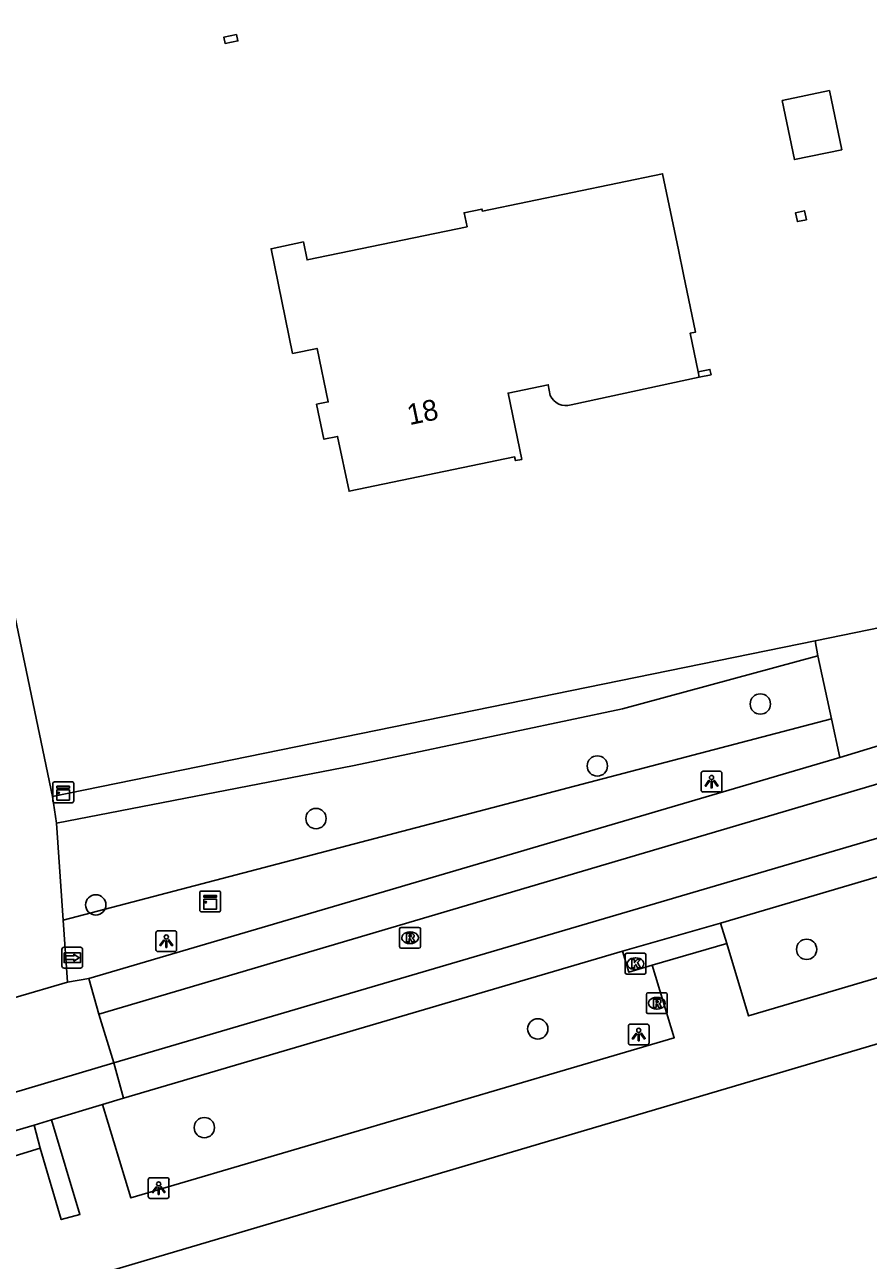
# Model space of a CAD drawing. Extents: x 162417 to 163721, y 384268 to 385416.
# Drawn here: x 163214.3 to 163254.9, y 384656 to 384715.4 of the extents above; entities that cross this region are included whole.
import ezdxf

# ---------------------------------------------------------------- set-up
doc = ezdxf.new("R2010")
doc.units = 0
for name, color, linetype in [('IMGEO_Boom', 7, 'Continuous'), ('IMGEO_Groenvoorziening', 7, 'Continuous'), ('IMGEO_Haag', 7, 'Continuous'), ('IMGEO_Kast', 7, 'Continuous'), ('IMGEO_Kolk', 7, 'Continuous'), ('IMGEO_Lichtpunt', 7, 'Continuous'), ('IMGEO_Muur', 7, 'Continuous'), ('IMGEO_Pand', 7, 'Continuous'), ('IMGEO_Pand_nummerreeks', 7, 'Continuous'), ('IMGEO_Rijbaan_lokaal_gesloten', 7, 'Continuous'), ('IMGEO_Rijbaan_lokaal_open', 7, 'Continuous'), ('IMGEO_Rioolput', 7, 'Continuous'), ('IMGEO_Voetpad_open', 7, 'Continuous'), ('IMGEO_Wegwijzer', 7, 'Continuous')]:
    doc.layers.add(name, color=color, linetype=linetype)

msp = doc.modelspace()

# ---------------------------------------------------------------- linework, layer by layer
at = {"layer": 'IMGEO_Boom'}
for centre in [(163249.675, 384682.735), (163241.835, 384679.753), (163228.302, 384677.22), (163217.707, 384673.066), (163251.902, 384670.927), (163238.971, 384667.097), (163222.929, 384662.346)]:
    msp.add_circle(centre, 0.489, dxfattribs=at)
at = {"layer": 'IMGEO_Groenvoorziening'}
msp.add_lwpolyline([(163253.099, 384682.014), (163216.145, 384672.327)], dxfattribs=at)
at = {"layer": 'IMGEO_Haag'}
for points in [[(163215.633, 384678.291), (163252.312, 384685.775)], [(163252.434, 384685.061), (163243.043, 384682.506), (163230.136, 384679.777), (163215.822, 384677.004)]]:
    msp.add_lwpolyline(points, dxfattribs=at)
at = {"layer": 'IMGEO_Kast'}
for p, q in [((163215.645, 384678.061), (163215.645, 384678.902)), ((163215.645, 384678.902), (163215.645, 384678.061)), ((163215.72, 384678.986), (163216.561, 384678.986)), ((163216.561, 384678.986), (163215.72, 384678.986)), ((163216.645, 384678.911), (163216.645, 384678.07)), ((163216.645, 384678.07), (163216.645, 384678.911)), ((163216.57, 384677.986), (163215.729, 384677.986)), ((163215.729, 384677.986), (163216.57, 384677.986)), ((163222.713, 384672.807), (163222.713, 384673.648)), ((163222.713, 384673.648), (163222.713, 384672.807)), ((163222.788, 384673.732), (163223.629, 384673.732)), ((163223.629, 384673.732), (163222.788, 384673.732)), ((163223.713, 384673.657), (163223.713, 384672.816)), ((163223.713, 384672.816), (163223.713, 384673.657)), ((163223.638, 384672.732), (163222.797, 384672.732)), ((163222.797, 384672.732), (163223.638, 384672.732))]:
    msp.add_line(p, q, dxfattribs=at)
for points in [[(163215.84, 384678.776), (163216.44, 384678.776), (163216.44, 384678.691), (163215.84, 384678.691), (163215.84, 384678.776)], [(163215.84, 384678.601), (163216.44, 384678.601), (163216.44, 384678.112), (163215.84, 384678.112), (163215.84, 384678.601)], [(163222.908, 384673.522), (163223.508, 384673.522), (163223.508, 384673.437), (163222.908, 384673.437), (163222.908, 384673.522)], [(163222.908, 384673.347), (163223.508, 384673.347), (163223.508, 384672.858), (163222.908, 384672.858), (163222.908, 384673.347)]]:
    msp.add_lwpolyline(points, dxfattribs=at)
for centre in [(163215.924, 384678.45), (163222.992, 384673.196)]:
    msp.add_circle(centre, 0.0377, dxfattribs=at)
for centre, start, end in [((163215.723, 384678.908), 92.4484, 184.28452), ((163215.723, 384678.908), 92.4484, 184.28452), ((163216.567, 384678.908), 2.4484, 94.28452), ((163216.567, 384678.908), 2.4484, 94.28452), ((163215.723, 384678.064), 182.4484, 274.28452), ((163215.723, 384678.064), 182.4484, 274.28452), ((163216.567, 384678.064), 272.4484, 4.28452), ((163216.567, 384678.064), 272.4484, 4.28452), ((163222.791, 384673.654), 92.4484, 184.28452), ((163222.791, 384673.654), 92.4484, 184.28452), ((163223.635, 384673.654), 2.4484, 94.28452), ((163223.635, 384673.654), 2.4484, 94.28452), ((163222.791, 384672.81), 182.4484, 274.28452), ((163222.791, 384672.81), 182.4484, 274.28452), ((163223.635, 384672.81), 272.4484, 4.28452), ((163223.635, 384672.81), 272.4484, 4.28452)]:
    msp.add_arc(centre, 0.0779, start, end, dxfattribs=at)
at = {"layer": 'IMGEO_Kolk'}
for p, q in [((163243.173, 384669.811), (163243.173, 384670.663)), ((163243.248, 384670.737), (163244.1, 384670.737)), ((163244.174, 384670.663), (163244.174, 384669.811)), ((163243.684, 384669.957), (163243.659, 384669.957)), ((163243.661, 384670.517), (163243.686, 384670.517)), ((163244.1, 384669.737), (163243.248, 384669.737))]:
    msp.add_line(p, q, dxfattribs=at)
for points in [[(163243.173, 384669.811), (163243.173, 384670.663)], [(163243.248, 384670.737), (163244.1, 384670.737)], [(163244.174, 384670.663), (163244.174, 384669.811)], [(163243.494, 384670.437), (163243.617, 384670.437), (163243.617, 384670.286), (163243.747, 384670.437), (163243.911, 384670.437), (163243.765, 384670.286), (163243.918, 384670.037), (163243.766, 384670.037), (163243.681, 384670.201), (163243.617, 384670.134), (163243.617, 384670.037), (163243.494, 384670.037), (163243.494, 384670.437)], [(163244.1, 384669.737), (163243.248, 384669.737)]]:
    msp.add_lwpolyline(points, dxfattribs=at)
for centre, start, end in [((163243.25, 384670.661), 91.55205, 178.44795), ((163243.25, 384670.661), 91.55205, 178.44795), ((163244.098, 384670.661), 1.55205, 88.44795), ((163244.098, 384670.661), 1.55205, 88.44795), ((163243.25, 384669.813), 181.55205, 268.44795), ((163243.25, 384669.813), 181.55205, 268.44795), ((163244.098, 384669.813), 271.55205, 358.44795), ((163244.098, 384669.813), 271.55205, 358.44795)]:
    msp.add_arc(centre, 0.0765, start, end, dxfattribs=at)
for centre, major_axis, ratio, start_param, end_param in [((163243.66, 384670.237), (-0.387, 0.002), 0.722429, 4.712389, 7.853982), ((163243.685, 384670.237), (-0.39, 0.002), 0.717154, 1.570796, 4.712389)]:
    msp.add_ellipse(centre, major_axis=major_axis, ratio=ratio, start_param=start_param, end_param=end_param, dxfattribs=at)
at = {"layer": 'IMGEO_Lichtpunt'}
for p, q in [((163247.731, 384679.496), (163246.923, 384679.496)), ((163247.731, 384679.496), (163246.923, 384679.496)), ((163246.829, 384679.401), (163246.829, 384678.594)), ((163246.829, 384679.401), (163246.829, 384678.594)), ((163247.825, 384678.594), (163247.825, 384679.401)), ((163247.825, 384678.594), (163247.825, 384679.401)), ((163246.923, 384678.5), (163247.731, 384678.5)), ((163246.923, 384678.5), (163247.731, 384678.5)), ((163221.504, 384671.818), (163220.696, 384671.818)), ((163221.504, 384671.818), (163220.696, 384671.818)), ((163220.602, 384671.723), (163220.602, 384670.916)), ((163220.602, 384671.723), (163220.602, 384670.916)), ((163221.598, 384670.916), (163221.598, 384671.723)), ((163221.598, 384670.916), (163221.598, 384671.723)), ((163220.696, 384670.822), (163221.504, 384670.822)), ((163220.696, 384670.822), (163221.504, 384670.822)), ((163243.327, 384667.232), (163243.327, 384666.425)), ((163243.327, 384667.232), (163243.327, 384666.425)), ((163244.229, 384667.327), (163243.421, 384667.327)), ((163244.229, 384667.327), (163243.421, 384667.327)), ((163244.323, 384666.425), (163244.323, 384667.232)), ((163244.323, 384666.425), (163244.323, 384667.232)), ((163243.421, 384666.331), (163244.229, 384666.331)), ((163243.421, 384666.331), (163244.229, 384666.331)), ((163221.136, 384659.934), (163220.328, 384659.934)), ((163221.136, 384659.934), (163220.328, 384659.934)), ((163220.234, 384659.839), (163220.234, 384659.032)), ((163220.234, 384659.839), (163220.234, 384659.032)), ((163221.23, 384659.032), (163221.23, 384659.839)), ((163221.23, 384659.032), (163221.23, 384659.839)), ((163220.328, 384658.938), (163221.136, 384658.938)), ((163220.328, 384658.938), (163221.136, 384658.938))]:
    msp.add_line(p, q, dxfattribs=at)
for points in [[(163247.203, 384679.065), (163247.242, 384679.037), (163247.054, 384678.775), (163247.016, 384678.802), (163247.203, 384679.065)], [(163247.305, 384679.017), (163247.352, 384679.017), (163247.352, 384678.695), (163247.305, 384678.695), (163247.305, 384679.017)], [(163247.415, 384679.037), (163247.453, 384679.064), (163247.64, 384678.802), (163247.601, 384678.774), (163247.415, 384679.037)], [(163220.976, 384671.387), (163221.015, 384671.359), (163220.827, 384671.097), (163220.789, 384671.124), (163220.976, 384671.387)], [(163221.078, 384671.339), (163221.125, 384671.339), (163221.125, 384671.017), (163221.078, 384671.017), (163221.078, 384671.339)], [(163221.188, 384671.359), (163221.226, 384671.386), (163221.413, 384671.124), (163221.374, 384671.096), (163221.188, 384671.359)], [(163243.701, 384666.896), (163243.74, 384666.868), (163243.552, 384666.606), (163243.514, 384666.633), (163243.701, 384666.896)], [(163243.803, 384666.848), (163243.85, 384666.848), (163243.85, 384666.526), (163243.803, 384666.526), (163243.803, 384666.848)], [(163243.913, 384666.868), (163243.951, 384666.895), (163244.138, 384666.633), (163244.099, 384666.605), (163243.913, 384666.868)], [(163220.608, 384659.503), (163220.647, 384659.475), (163220.459, 384659.213), (163220.421, 384659.24), (163220.608, 384659.503)], [(163220.71, 384659.455), (163220.757, 384659.455), (163220.757, 384659.133), (163220.71, 384659.133), (163220.71, 384659.455)], [(163220.82, 384659.475), (163220.858, 384659.502), (163221.045, 384659.24), (163221.006, 384659.212), (163220.82, 384659.475)]]:
    msp.add_lwpolyline(points, dxfattribs=at)
for centre in [(163247.328, 384679.199), (163221.101, 384671.521), (163243.826, 384667.03), (163220.733, 384659.637)]:
    msp.add_circle(centre, 0.0994, dxfattribs=at)
for centre, start, end in [((163246.923, 384679.401), 90, 180), ((163246.923, 384679.401), 90, 180), ((163247.731, 384679.401), 0, 90), ((163247.731, 384679.401), 0, 90), ((163246.923, 384678.594), 180, 270), ((163246.923, 384678.594), 180, 270), ((163247.731, 384678.594), 270, 0), ((163247.731, 384678.594), 270, 360), ((163220.696, 384671.723), 90, 180), ((163220.696, 384671.723), 90, 180), ((163221.504, 384671.723), 0, 90), ((163221.504, 384671.723), 0, 90), ((163220.696, 384670.916), 180, 270), ((163220.696, 384670.916), 180, 270), ((163221.504, 384670.916), 270, 0), ((163221.504, 384670.916), 270, 360), ((163243.421, 384667.232), 90, 180), ((163243.421, 384667.232), 90, 180), ((163244.229, 384667.232), 0, 90), ((163244.229, 384667.232), 0, 90), ((163243.421, 384666.425), 180, 270), ((163243.421, 384666.425), 180, 270), ((163244.229, 384666.425), 270, 0), ((163244.229, 384666.425), 270, 360), ((163220.328, 384659.839), 90, 180), ((163220.328, 384659.839), 90, 180), ((163221.136, 384659.839), 0, 90), ((163221.136, 384659.839), 0, 90), ((163220.328, 384659.032), 180, 270), ((163220.328, 384659.032), 180, 270), ((163221.136, 384659.032), 270, 0), ((163221.136, 384659.032), 270, 360)]:
    msp.add_arc(centre, 0.0946, start, end, dxfattribs=at)
at = {"layer": 'IMGEO_Muur'}
msp.add_lwpolyline([(163246.68, 384698.723), (163247.253, 384698.842), (163247.307, 384698.584), (163246.734, 384698.461)], dxfattribs=at)
at = {"layer": 'IMGEO_Pand'}
for points in [[(163224.481, 384714.954), (163224.542, 384714.65), (163223.925, 384714.525), (163223.864, 384714.829), (163224.481, 384714.954)], [(163250.725, 384711.789), (163252.996, 384712.261), (163253.588, 384709.41), (163251.317, 384708.938), (163250.725, 384711.789)], [(163239.572, 384697.588), (163239.475, 384698.099), (163237.539, 384697.697), (163238.201, 384694.51), (163237.895, 384694.447), (163237.857, 384694.629), (163229.891, 384692.975), (163229.342, 384695.615), (163228.682, 384695.478), (163228.333, 384697.158), (163228.888, 384697.273), (163228.352, 384699.853), (163227.175, 384699.609), (163226.141, 384704.649), (163227.693, 384704.971), (163227.873, 384704.106), (163235.565, 384705.703), (163235.425, 384706.379), (163236.286, 384706.557), (163236.307, 384706.456), (163244.973, 384708.255), (163245.733, 384704.596), (163245.979, 384703.413), (163246.556, 384700.63), (163246.295, 384700.576), (163246.68, 384698.723)], [(163251.888, 384706.042), (163251.458, 384705.95), (163251.368, 384706.381), (163251.798, 384706.473), (163251.888, 384706.042)], [(163246.68, 384698.723), (163246.734, 384698.461)], [(163246.734, 384698.461), (163240.571, 384697.135)]]:
    msp.add_lwpolyline(points, dxfattribs=at)
msp.add_arc((163240.324, 384697.918), 0.821, 203.68123, 287.53461, dxfattribs=at)
at = {"layer": 'IMGEO_Rijbaan_lokaal_gesloten'}
for points in [[(163289.922, 384689.131), (163217.858, 384667.814)], [(163218.569, 384665.465), (163290.633, 384686.675)], [(163253.504, 384680.159), (163257.233, 384681.296)], [(163217.379, 384669.518), (163253.504, 384680.159)], [(163263.667, 384676.895), (163247.767, 384672.179)], [(163247.767, 384672.179), (163243.04, 384670.847)], [(163243.04, 384670.847), (163219.046, 384663.763)], [(163219.046, 384663.763), (163218.569, 384665.465)], [(163218.038, 384663.465), (163215.573, 384662.717)], [(163219.046, 384663.763), (163218.038, 384663.465)], [(163210.145, 384661.119), (163214.749, 384662.457)], [(163214.749, 384662.457), (163215.573, 384662.717)]]:
    msp.add_lwpolyline(points, dxfattribs=at)
at = {"layer": 'IMGEO_Rijbaan_lokaal_open'}
for points in [[(163216.351, 384669.353), (163217.379, 384669.518)], [(163217.858, 384667.814), (163217.379, 384669.518)], [(163213.831, 384668.612), (163216.351, 384669.353)], [(163218.569, 384665.465), (163217.858, 384667.814)], [(163199.311, 384659.719), (163218.569, 384665.465)]]:
    msp.add_lwpolyline(points, dxfattribs=at)
at = {"layer": 'IMGEO_Rioolput'}
for p, q in [((163232.325, 384671.059), (163232.325, 384671.911)), ((163232.4, 384671.985), (163233.252, 384671.985)), ((163232.813, 384671.765), (163232.838, 384671.765)), ((163233.326, 384671.911), (163233.326, 384671.059)), ((163232.836, 384671.205), (163232.811, 384671.205)), ((163233.252, 384670.985), (163232.4, 384670.985)), ((163244.271, 384668.835), (163245.123, 384668.835)), ((163244.196, 384667.909), (163244.196, 384668.761)), ((163244.684, 384668.615), (163244.709, 384668.615)), ((163245.197, 384668.761), (163245.197, 384667.909)), ((163245.123, 384667.835), (163244.271, 384667.835)), ((163244.707, 384668.055), (163244.682, 384668.055))]:
    msp.add_line(p, q, dxfattribs=at)
for points in [[(163232.325, 384671.059), (163232.325, 384671.911)], [(163232.4, 384671.985), (163233.252, 384671.985)], [(163233.326, 384671.911), (163233.326, 384671.059)], [(163232.914, 384671.683), (163232.662, 384671.685), (163232.662, 384671.285)], [(163232.662, 384671.285), (163232.786, 384671.285), (163232.786, 384671.447), (163232.797, 384671.447)], [(163232.84, 384671.604), (163232.786, 384671.604), (163232.786, 384671.523)], [(163232.786, 384671.523), (163232.838, 384671.523)], [(163232.844, 384671.418), (163232.915, 384671.285), (163233.055, 384671.285), (163232.99, 384671.411)], [(163233.252, 384670.985), (163232.4, 384670.985)], [(163244.271, 384668.835), (163245.123, 384668.835)], [(163244.196, 384667.909), (163244.196, 384668.761)], [(163244.785, 384668.533), (163244.533, 384668.535), (163244.533, 384668.135)], [(163244.533, 384668.135), (163244.657, 384668.135), (163244.657, 384668.297), (163244.668, 384668.297)], [(163244.711, 384668.454), (163244.657, 384668.454), (163244.657, 384668.373)], [(163244.657, 384668.373), (163244.709, 384668.373)], [(163244.715, 384668.268), (163244.786, 384668.135), (163244.926, 384668.135), (163244.861, 384668.261)], [(163245.197, 384668.761), (163245.197, 384667.909)], [(163245.123, 384667.835), (163244.271, 384667.835)]]:
    msp.add_lwpolyline(points, dxfattribs=at)
for centre, radius, start, end in [((163232.402, 384671.909), 0.0765, 91.55205, 178.44795), ((163232.402, 384671.909), 0.0765, 91.55205, 178.44795), ((163233.25, 384671.909), 0.0765, 1.55205, 88.44795), ((163233.25, 384671.909), 0.0765, 1.55205, 88.44795), ((163232.796, 384671.394), 0.0533, 26.02933, 88.69889), ((163232.822, 384671.712), 0.19, 274.7715, 282.96867), ((163232.846, 384671.508), 0.0964, 77.00612, 93.18647), ((163232.86, 384671.565), 0.0378, 276.66336, 79.67722), ((163232.913, 384671.573), 0.109, 350.36119, 89.41601), ((163232.911, 384671.573), 0.112, 277.58423, 350.98172), ((163232.895, 384671.358), 0.108, 29.51342, 73.79051), ((163232.402, 384671.061), 0.0765, 181.55205, 268.44795), ((163232.402, 384671.061), 0.0765, 181.55205, 268.44795), ((163233.25, 384671.061), 0.0765, 271.55205, 358.44795), ((163233.25, 384671.061), 0.0765, 271.55205, 358.44795), ((163244.273, 384668.759), 0.0765, 91.55205, 178.44795), ((163244.273, 384668.759), 0.0765, 91.55205, 178.44795), ((163245.121, 384668.759), 0.0765, 1.55205, 88.44795), ((163245.121, 384668.759), 0.0765, 1.55205, 88.44795), ((163244.667, 384668.244), 0.0533, 26.02933, 88.69889), ((163244.693, 384668.562), 0.19, 274.7715, 282.96867), ((163244.717, 384668.358), 0.0964, 77.00612, 93.18647), ((163244.731, 384668.415), 0.0378, 276.66336, 79.67722), ((163244.784, 384668.423), 0.109, 350.36119, 89.41601), ((163244.782, 384668.423), 0.112, 277.58423, 350.98172), ((163244.766, 384668.208), 0.108, 29.51342, 73.79051), ((163244.273, 384667.911), 0.0765, 181.55205, 268.44795), ((163244.273, 384667.911), 0.0765, 181.55205, 268.44795), ((163245.121, 384667.911), 0.0765, 271.55205, 358.44795), ((163245.121, 384667.911), 0.0765, 271.55205, 358.44795)]:
    msp.add_arc(centre, radius, start, end, dxfattribs=at)
for centre, major_axis, ratio, start_param, end_param in [((163232.812, 384671.485), (-0.387, 0.002), 0.722429, 4.712389, 7.853982), ((163232.837, 384671.485), (-0.39, 0.002), 0.717154, 1.570796, 4.712389), ((163244.683, 384668.335), (-0.387, 0.002), 0.722429, 4.712389, 7.853982), ((163244.708, 384668.335), (-0.39, 0.002), 0.717154, 1.570796, 4.712389)]:
    msp.add_ellipse(centre, major_axis=major_axis, ratio=ratio, start_param=start_param, end_param=end_param, dxfattribs=at)
at = {"layer": 'IMGEO_Voetpad_open'}
for points in [[(163224.144, 384802.92), (163192.437, 384789.411), (163200.664, 384750), (163215.633, 384678.291)], [(163252.312, 384685.775), (163256.147, 384686.557)], [(163252.312, 384685.775), (163252.434, 384685.061)], [(163252.434, 384685.061), (163253.099, 384682.014)], [(163253.099, 384682.014), (163253.504, 384680.159)], [(163162.154, 384638.801), (163211.589, 384653.439), (163217.164, 384655.09), (163299.946, 384679.602)], [(163215.822, 384677.004), (163215.633, 384678.291)], [(163215.822, 384677.004), (163216.145, 384672.327)], [(163248.057, 384671.212), (163249.111, 384667.719), (163266.1, 384672.742), (163265.056, 384676.225)], [(163216.145, 384672.327), (163216.351, 384669.353)], [(163247.767, 384672.179), (163248.057, 384671.212)], [(163248.057, 384671.212), (163244.471, 384670.163)], [(163244.471, 384670.163), (163243.346, 384669.828), (163243.04, 384670.847)], [(163218.038, 384663.465), (163219.395, 384658.96), (163245.534, 384666.668), (163244.471, 384670.163)], [(163215.04, 384661.365), (163214.749, 384662.457)], [(163215.573, 384662.717), (163216.941, 384658.171), (163216.049, 384657.922), (163215.04, 384661.365)], [(163215.04, 384661.365), (163211.624, 384660.318)]]:
    msp.add_lwpolyline(points, dxfattribs=at)
at = {"layer": 'IMGEO_Wegwijzer'}
for p, q in [((163216.082, 384670.125), (163216.082, 384670.925)), ((163216.082, 384670.925), (163216.082, 384670.125)), ((163216.182, 384671.025), (163216.972, 384671.025)), ((163216.972, 384671.025), (163216.182, 384671.025)), ((163217.072, 384670.925), (163217.072, 384670.125)), ((163217.072, 384670.125), (163217.072, 384670.925)), ((163216.972, 384670.025), (163216.182, 384670.025)), ((163216.182, 384670.025), (163216.972, 384670.025))]:
    msp.add_line(p, q, dxfattribs=at)
for points in [[(163216.183, 384670.757), (163216.971, 384670.757), (163216.971, 384670.293), (163216.183, 384670.293), (163216.183, 384670.757)], [(163216.248, 384670.609), (163216.248, 384670.525), (163216.248, 384670.441), (163216.659, 384670.441), (163216.659, 384670.358), (163216.906, 384670.525), (163216.659, 384670.692), (163216.659, 384670.609), (163216.248, 384670.609)]]:
    msp.add_lwpolyline(points, dxfattribs=at)
for centre, start, end in [((163216.182, 384670.925), 90, 180), ((163216.182, 384670.925), 90, 180), ((163216.972, 384670.925), 0, 90), ((163216.972, 384670.925), 360, 90), ((163216.182, 384670.125), 180, 270), ((163216.182, 384670.125), 180, 270), ((163216.972, 384670.125), 270, 0), ((163216.972, 384670.125), 270, 0)]:
    msp.add_arc(centre, 0.1, start, end, dxfattribs=at)

# ---------------------------------------------------------------- texts
at = {"layer": 'IMGEO_Pand_nummerreeks'}
msp.add_text('18', height=1, rotation=11.72845, dxfattribs=at).set_placement((163232.797, 384696.152))

doc.saveas('drawing.dxf')
